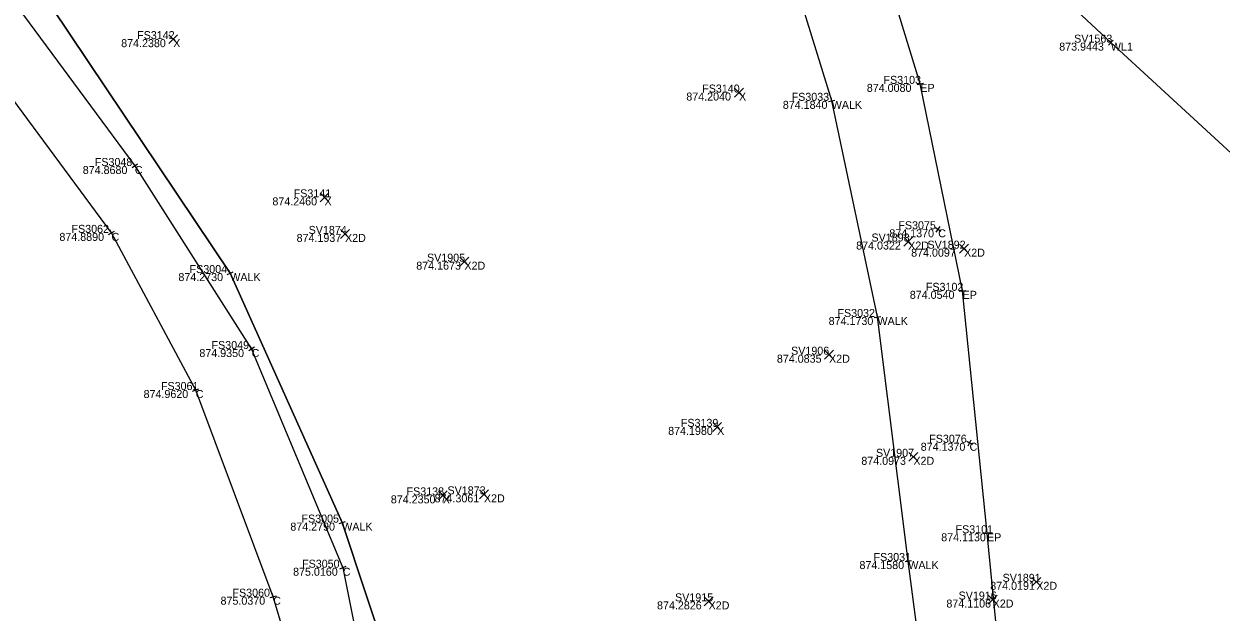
# Model space of a CAD drawing. Extents: x 1479481 to 1575806, y 316056 to 379927.
# Drawn here: x 1480136.78 to 1480145.75, y 379416.75 to 379421.16 of the extents above; entities that cross this region are included whole.
import ezdxf

# ---------------------------------------------------------------- set-up
doc = ezdxf.new("R2010")
doc.units = 0
for name, color, linetype in [('PV_X_Curb', 7, 'Continuous'), ('PV_X_Walk', 7, 'Continuous'), ('SV_X_Random_Point', 7, 'Continuous'), ('SV_X_Shot_Marker', 7, 'Continuous'), ('SV_X_Text_Comment', 7, 'Continuous'), ('SV_X_Text_Elevation', 7, 'Continuous'), ('SV_X_Text_Name', 7, 'Continuous'), ('UT_X_Water', 7, 'Continuous')]:
    doc.layers.add(name, color=color, linetype=linetype)

msp = doc.modelspace()

# ---------------------------------------------------------------- linework, layer by layer
at = {"layer": 'PV_X_Curb'}
for points in [[(1480144.119, 379408.6925), (1480144.24, 379410.484), (1480144.247, 379412.184), (1480144.2756, 379413.7273), (1480144.183, 379415.462), (1480143.996, 379417.344), (1480143.813, 379419.16), (1480143.496, 379420.71), (1480143.015, 379422.278), (1480142.354, 379423.817), (1480141.636, 379425.054), (1480140.711, 379426.236), (1480139.646, 379427.551), (1480138.485, 379428.822), (1480137.236, 379430.074), (1480137.133, 379430.2922), (1480135.667, 379431.559), (1480135.19, 379432.3319), (1480118.45, 379448.1601)], [(1480143.467, 379408.427), (1480143.491, 379410.102), (1480143.626, 379411.891), (1480143.667, 379412.715), (1480143.643, 379414.145), (1480143.592, 379415.709), (1480143.406, 379417.136), (1480143.175, 379418.964), (1480142.832, 379420.583), (1480142.491, 379421.692), (1480141.812, 379423.272), (1480140.724, 379425.16), (1480139.421, 379426.804), (1480138.202, 379428.161), (1480136.669, 379429.706), (1480137.1142, 379430.0955), (1480136.349, 379430.778), (1480135, 379431.8972), (1480118.039, 379447.9143)], [(1480132.735, 379425.624), (1480133.489, 379424.793), (1480135.438, 379422.771), (1480136.612, 379421.448), (1480137.609, 379420.095), (1480138.484, 379418.724), (1480139.167, 379417.086), (1480139.644, 379414.697), (1480139.873, 379412.175), (1480139.928, 379410.1), (1480139.896, 379409.023), (1480139.487, 379409.126), (1480139.398, 379410.762), (1480139.445, 379412.342), (1480139.28, 379413.822), (1480139.072, 379415.451), (1480138.646, 379416.869), (1480138.065, 379418.417), (1480137.434, 379419.594), (1480136.416, 379420.968), (1480135.065, 379422.458), (1480133.739, 379423.908), (1480132.463, 379425.289)]]:
    msp.add_lwpolyline(points, dxfattribs=at)
at = {"layer": 'PV_X_Walk'}
for points in [[(1480121.511, 379381.7697), (1480134.604, 379395.5795), (1480136.695, 379398.1481), (1480138.804, 379401.064), (1480139.196, 379402.304), (1480139.794, 379404.164), (1480140.245, 379405.64), (1480140.457, 379406.671), (1480140.54, 379407.685), (1480140.6844, 379408.9816), (1480140.078, 379409.022), (1480140.106, 379411.022), (1480140.05, 379412.608), (1480139.852, 379414.468), (1480139.524, 379416.334), (1480139.163, 379417.424), (1480138.324, 379419.293), (1480136.856, 379421.479), (1480135.693, 379422.823), (1480134.581, 379423.922), (1480132.876, 379425.614), (1480132.82, 379425.698), (1480131.146, 379427.408), (1480114.834, 379442.9595)], [(1480143.467, 379408.427), (1480143.491, 379410.102), (1480143.626, 379411.891), (1480143.667, 379412.715), (1480143.643, 379414.145), (1480143.592, 379415.709), (1480143.406, 379417.136), (1480143.175, 379418.964), (1480142.832, 379420.583), (1480142.491, 379421.692), (1480141.812, 379423.272), (1480140.724, 379425.16), (1480139.421, 379426.804), (1480138.202, 379428.161), (1480136.669, 379429.706), (1480135.545, 379428.421), (1480134.397, 379429.433)], [(1480132.876, 379425.614), (1480134.581, 379423.922), (1480135.693, 379422.823), (1480136.856, 379421.479), (1480138.324, 379419.293), (1480139.163, 379417.424), (1480139.524, 379416.334), (1480139.852, 379414.468), (1480140.05, 379412.608), (1480140.106, 379411.022), (1480140.078, 379409.022), (1480140.6844, 379408.9816), (1480140.54, 379407.685)]]:
    msp.add_lwpolyline(points, dxfattribs=at)
at = {"layer": 'SV_X_Random_Point'}
for p, q in [((1480137.8627, 379421.0116), (1480137.9293, 379421.0784)), ((1480137.8627, 379421.0784), (1480137.9293, 379421.0116)), ((1480142.1037, 379420.6116), (1480142.1703, 379420.6784)), ((1480142.1037, 379420.6784), (1480142.1703, 379420.6116)), ((1480138.9967, 379419.8266), (1480139.0633, 379419.8934)), ((1480138.9967, 379419.8934), (1480139.0633, 379419.8266)), ((1480139.1507, 379419.5528), (1480139.2173, 379419.6196)), ((1480139.1507, 379419.6196), (1480139.2173, 379419.5528)), ((1480143.3717, 379419.4957), (1480143.4383, 379419.5625)), ((1480143.3717, 379419.5625), (1480143.4383, 379419.4957)), ((1480143.7907, 379419.4422), (1480143.8573, 379419.509)), ((1480143.7907, 379419.509), (1480143.8573, 379419.4422)), ((1480140.0457, 379419.345), (1480140.1123, 379419.4118)), ((1480140.0457, 379419.4118), (1480140.1123, 379419.345)), ((1480142.7787, 379418.6481), (1480142.8453, 379418.7149)), ((1480142.7787, 379418.7149), (1480142.8453, 379418.6481)), ((1480141.9397, 379418.1076), (1480142.0063, 379418.1744)), ((1480141.9397, 379418.1744), (1480142.0063, 379418.1076)), ((1480143.4107, 379417.8833), (1480143.4773, 379417.9501)), ((1480143.4107, 379417.9501), (1480143.4773, 379417.8833)), ((1480139.8837, 379417.5946), (1480139.9503, 379417.6614)), ((1480139.8837, 379417.6614), (1480139.9503, 379417.5946)), ((1480140.1917, 379417.6023), (1480140.2583, 379417.6691)), ((1480140.1917, 379417.6691), (1480140.2583, 379417.6023)), ((1480144.3317, 379416.9471), (1480144.3983, 379417.0139)), ((1480144.3317, 379417.0139), (1480144.3983, 379416.9471)), ((1480141.8757, 379416.8007), (1480141.9423, 379416.8675)), ((1480141.8757, 379416.8675), (1480141.9423, 379416.8007)), ((1480144.0047, 379416.8143), (1480144.0713, 379416.8811)), ((1480144.0047, 379416.8811), (1480144.0713, 379416.8143))]:
    msp.add_line(p, q, dxfattribs=at)
at = {"layer": 'SV_X_Shot_Marker'}
for p, q in [((1480144.9424, 379421.002), (1480144.9056, 379421.0358)), ((1480144.9071, 379421.0005), (1480144.9409, 379421.0373)), ((1480144.924, 379421.0189), (1480144.924, 379421.0189)), ((1480143.4715, 379420.705), (1480143.5205, 379420.715)), ((1480143.501, 379420.6855), (1480143.491, 379420.7345)), ((1480143.496, 379420.71), (1480143.496, 379420.71)), ((1480142.8372, 379420.5586), (1480142.8268, 379420.6075)), ((1480142.8075, 379420.5778), (1480142.8565, 379420.5882)), ((1480142.832, 379420.583), (1480142.832, 379420.583)), ((1480137.6291, 379420.1098), (1480137.5889, 379420.0802)), ((1480137.5942, 379420.1151), (1480137.6238, 379420.0749)), ((1480137.609, 379420.095), (1480137.609, 379420.095)), ((1480137.412, 379419.5822), (1480137.456, 379419.6058)), ((1480137.4458, 379419.572), (1480137.4222, 379419.616)), ((1480143.6094, 379419.6352), (1480143.6506, 379419.6068)), ((1480143.6158, 379419.6005), (1480143.6442, 379419.6416)), ((1480143.63, 379419.621), (1480143.63, 379419.621)), ((1480137.434, 379419.594), (1480137.434, 379419.594)), ((1480138.3012, 379419.2828), (1480138.3468, 379419.3032)), ((1480138.3342, 379419.2702), (1480138.3138, 379419.3158)), ((1480138.324, 379419.293), (1480138.324, 379419.293)), ((1480143.7881, 379419.1575), (1480143.8379, 379419.1625)), ((1480143.8155, 379419.1351), (1480143.8105, 379419.1849)), ((1480143.813, 379419.16), (1480143.813, 379419.16)), ((1480143.1781, 379418.9392), (1480143.1719, 379418.9888)), ((1480143.1502, 379418.9609), (1480143.1998, 379418.9671)), ((1480143.175, 379418.964), (1480143.175, 379418.964)), ((1480138.5051, 379418.7375), (1480138.4629, 379418.7106)), ((1480138.4706, 379418.7451), (1480138.4974, 379418.7029)), ((1480138.484, 379418.724), (1480138.484, 379418.724)), ((1480138.0738, 379418.3936), (1480138.0562, 379418.4404)), ((1480138.0416, 379418.4082), (1480138.0884, 379418.4258)), ((1480138.065, 379418.417), (1480138.065, 379418.417)), ((1480143.8428, 379418.0335), (1480143.8872, 379418.0105)), ((1480143.8535, 379417.9998), (1480143.8765, 379418.0442)), ((1480143.865, 379418.022), (1480143.865, 379418.022)), ((1480139.1393, 379417.4162), (1480139.1867, 379417.4319)), ((1480139.1709, 379417.4003), (1480139.1551, 379417.4477)), ((1480139.163, 379417.424), (1480139.163, 379417.424)), ((1480143.9985, 379417.3191), (1480143.9935, 379417.3689)), ((1480143.9711, 379417.3415), (1480144.0209, 379417.3465)), ((1480143.996, 379417.344), (1480143.996, 379417.344)), ((1480139.1901, 379417.0956), (1480139.1439, 379417.0764)), ((1480139.1574, 379417.1091), (1480139.1766, 379417.0629)), ((1480143.3812, 379417.1328), (1480143.4308, 379417.1392)), ((1480143.4092, 379417.1112), (1480143.4028, 379417.1608)), ((1480143.406, 379417.136), (1480143.406, 379417.136)), ((1480139.167, 379417.086), (1480139.167, 379417.086)), ((1480138.6221, 379416.8618), (1480138.6699, 379416.8762)), ((1480138.6532, 379416.8451), (1480138.6388, 379416.893)), ((1480138.646, 379416.869), (1480138.646, 379416.869))]:
    msp.add_line(p, q, dxfattribs=at)
at = {"layer": 'UT_X_Water'}
msp.add_lwpolyline([(1480234.677, 379335.8629), (1480225.088, 379345.6014), (1480208.322, 379361.3416), (1480207.346, 379362.2502), (1480199.528, 379369.7682), (1480193.21, 379375.6513), (1480182.823, 379385.1388), (1480177.927, 379389.5245), (1480169.423, 379398.3206), (1480161.035, 379406.1892), (1480144.924, 379421.0189), (1480134.739, 379430.5593), (1480121.485, 379441.9981), (1480113.085, 379450.3693), (1480106.418, 379456.9146), (1480094.539, 379467.9854), (1480089.15, 379472.5509), (1480086.751, 379474.7134), (1480073.459, 379487.3367), (1480068.123, 379493.1874), (1480050.678, 379510.2071), (1480044.404, 379515.873)], dxfattribs=at)

# ---------------------------------------------------------------- texts
at = {"layer": 'SV_X_Text_Comment'}
for s, p in [('X', (1480137.896, 379420.985)), ('WL1', (1480144.924, 379420.9589)), ('EP', (1480143.496, 379420.65)), ('X', (1480142.137, 379420.585)), ('WALK', (1480142.832, 379420.523)), ('C', (1480137.609, 379420.035)), ('X', (1480139.03, 379419.8)), ('C', (1480143.63, 379419.561)), ('C', (1480137.434, 379419.534)), ('X2D', (1480139.184, 379419.5262)), ('X2D', (1480143.405, 379419.4691)), ('X2D', (1480143.824, 379419.4156)), ('X2D', (1480140.079, 379419.3184)), ('WALK', (1480138.324, 379419.233)), ('EP', (1480143.813, 379419.1)), ('WALK', (1480143.175, 379418.904)), ('C', (1480138.484, 379418.664)), ('X2D', (1480142.812, 379418.6215)), ('C', (1480138.065, 379418.357)), ('X', (1480141.973, 379418.081)), ('C', (1480143.865, 379417.962)), ('X2D', (1480143.444, 379417.8567)), ('X2D', (1480140.225, 379417.5757)), ('X', (1480139.917, 379417.568)), ('WALK', (1480139.163, 379417.364)), ('EP', (1480143.996, 379417.284)), ('WALK', (1480143.406, 379417.076)), ('C', (1480139.167, 379417.026)), ('X2D', (1480144.365, 379416.9205)), ('C', (1480138.646, 379416.809)), ('X2D', (1480141.909, 379416.7741)), ('X2D', (1480144.038, 379416.7877))]:
    msp.add_text(s, height=0.06, dxfattribs=at).set_placement(p)
at = {"layer": 'SV_X_Text_Elevation'}
for s, p in [('874.2380', (1480137.5063, 379420.985)), ('873.9443', (1480144.5371, 379420.9589)), ('874.0080', (1480143.0949, 379420.65)), ('874.2040', (1480141.7421, 379420.585)), ('874.1840', (1480142.4654, 379420.523)), ('874.8680', (1480137.2183, 379420.035)), ('874.2460', (1480138.6398, 379419.8)), ('874.1370', (1480143.2639, 379419.561)), ('874.8890', (1480137.0433, 379419.534)), ('874.1937', (1480138.8212, 379419.5262)), ('874.0322', (1480143.0153, 379419.4691)), ('874.0097', (1480143.4272, 379419.4156)), ('874.1673', (1480139.7181, 379419.3184)), ('874.2730', (1480137.9352, 379419.233)), ('874.0540', (1480143.4171, 379419.1)), ('874.1730', (1480142.8089, 379418.904)), ('874.9350', (1480138.0924, 379418.664)), ('874.0835', (1480142.4209, 379418.6215)), ('874.9620', (1480137.6743, 379418.357)), ('874.1980', (1480141.606, 379418.081)), ('874.1370', (1480143.4989, 379417.962)), ('874.0973', (1480143.0538, 379417.8567)), ('874.3061', (1480139.8555, 379417.5757)), ('874.2350', (1480139.5273, 379417.568)), ('874.2790', (1480138.7742, 379417.364)), ('874.1130', (1480143.6526, 379417.284)), ('874.1580', (1480143.0399, 379417.076)), ('875.0160', (1480138.7948, 379417.026)), ('874.0191', (1480144.0201, 379416.9205)), ('875.0370', (1480138.2511, 379416.809)), ('874.2826', (1480141.5226, 379416.7741)), ('874.1106', (1480143.6913, 379416.7877))]:
    msp.add_text(s, height=0.06, dxfattribs=at).set_placement(p)
at = {"layer": 'SV_X_Text_Name'}
for s, p in [('FS3142', (1480137.6258, 379421.045)), ('SV1563', (1480144.6491, 379421.0189)), ('FS3140', (1480141.8611, 379420.645)), ('FS3103', (1480143.2201, 379420.71)), ('FS3033', (1480142.5316, 379420.583)), ('FS3048', (1480137.3086, 379420.095)), ('FS3141', (1480138.7993, 379419.86)), ('FS3062', (1480137.134, 379419.594)), ('SV1874', (1480138.9115, 379419.5862)), ('FS3075', (1480143.3314, 379419.621)), ('SV1893', (1480143.1301, 379419.5291)), ('SV1892', (1480143.5496, 379419.4756)), ('SV1905', (1480139.7984, 379419.3784)), ('FS3004', (1480138.0193, 379419.293)), ('FS3102', (1480143.5376, 379419.16)), ('FS3032', (1480142.875, 379418.964)), ('FS3049', (1480138.1836, 379418.724)), ('SV1906', (1480142.5276, 379418.6815)), ('FS3061', (1480137.8045, 379418.417)), ('FS3139', (1480141.7014, 379418.141)), ('FS3076', (1480143.5627, 379418.022)), ('SV1907', (1480143.1634, 379417.9167)), ('FS3138', (1480139.6454, 379417.628)), ('SV1873', (1480139.952, 379417.6357)), ('FS3005', (1480138.8578, 379417.424)), ('FS3101', (1480143.7601, 379417.344)), ('FS3031', (1480143.1455, 379417.136)), ('FS3050', (1480138.8623, 379417.086)), ('SV1891', (1480144.1127, 379416.9805)), ('FS3060', (1480138.3404, 379416.869)), ('SV1915', (1480141.6577, 379416.8341)), ('SV1916', (1480143.783, 379416.8477))]:
    msp.add_text(s, height=0.06, dxfattribs=at).set_placement(p)

doc.saveas('drawing.dxf')
